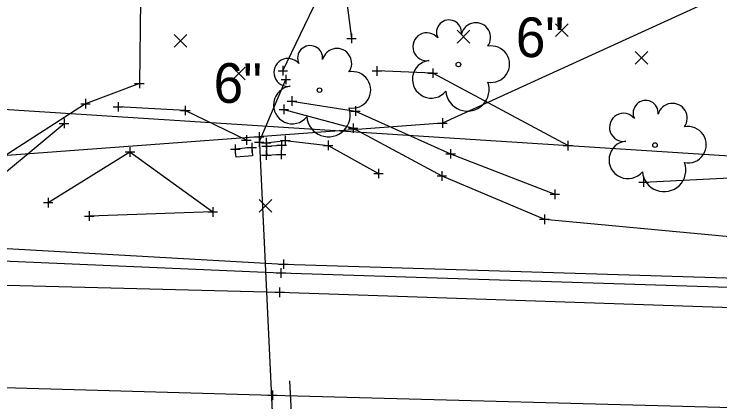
# Model space of a CAD drawing. Extents: x 2005176 to 2005823, y 572472 to 572942.
# Drawn here: x 2005497.2 to 2005571.3, y 572608.1 to 572648.8 of the extents above; entities that cross this region are included whole.
import ezdxf

# ---------------------------------------------------------------- set-up
doc = ezdxf.new("R2010")
doc.units = 0
for name, color, linetype in [('_CIVIL_CONSTRUCTION', 7, 'Continuous'), ('DR_X_Storm_Sewer', 7, 'Continuous'), ('DR_X_Text', 7, 'Continuous'), ('GE_X_Alignment_1000_Bearings', 7, 'Continuous'), ('GE_X_Alignment_1000_Cardinal_Points', 7, 'Continuous'), ('GE_X_Alignment_1000_Curve_Data', 7, 'Continuous'), ('GE_X_Alignment_100_Bearings', 7, 'Continuous'), ('GE_X_Alignment_100_Cardinal_Points', 7, 'Continuous'), ('GE_X_Alignment_100_Distances', 7, 'Continuous'), ('GE_X_Alignment_100_Stations', 7, 'Continuous'), ('GE_X_Alignment_500_Bearings', 7, 'Continuous'), ('GE_X_Alignment_500_Distances', 7, 'Continuous'), ('SC_Scratch10', 7, 'Continuous'), ('SC_Scratch8', 7, 'Continuous'), ('SV_P_Mon_Cells_Set', 7, 'Continuous'), ('SV_X_Random_Point', 7, 'Continuous'), ('SV_X_Shot_Marker', 7, 'Continuous'), ('VG_X_Text', 7, 'Continuous')]:
    doc.layers.add(name, color=color, linetype=linetype)

msp = doc.modelspace()

# ---------------------------------------------------------------- linework, layer by layer
at = {"layer": '_CIVIL_CONSTRUCTION'}
for p, q in [((2005525.415, 572643.362), (2005525.415, 572642.362)), ((2005524.915, 572642.862), (2005525.915, 572642.862)), ((2005525.415, 572642.862), (2005525.415, 572642.862)), ((2005522.925, 572636.417), (2005522.925, 572635.417)), ((2005522.425, 572635.917), (2005523.425, 572635.917)), ((2005522.925, 572635.917), (2005522.925, 572635.917))]:
    msp.add_line(p, q, dxfattribs=at)
at = {"layer": 'DR_X_Storm_Sewer'}
for p, q in [((2005525.415, 572642.862), (2005551.774, 572697.546)), ((2005522.925, 572635.917), (2005526.039, 572569.63))]:
    msp.add_line(p, q, dxfattribs=at)
at = {"layer": 'DR_X_Text'}
msp.add_line((2005527.042, 572591.446), (2005526.156, 572610.296), dxfattribs=at)
at = {"layer": 'GE_X_Alignment_1000_Bearings'}
msp.add_lwpolyline([(2005377.362, 572646.47), (2005740.514, 572623.098)], dxfattribs=at)
at = {"layer": 'GE_X_Alignment_1000_Cardinal_Points'}
msp.add_lwpolyline([(2005589.359, 572669.576), (2005577.827, 572653.684), (2005542.162, 572637.376), (2005475.268, 572632.406), (2005412.503, 572639.628), (2005455.372, 572649.173), (2005453.824, 572664.208)], dxfattribs=at)
at = {"layer": 'GE_X_Alignment_1000_Curve_Data'}
for p, q in [((2005522.149, 572634.791), (2005522.221, 572633.915)), ((2005523.761, 572633.979), (2005523.715, 572634.946)), ((2005520.512, 572633.775), (2005520.422, 572634.628)), ((2005525.234, 572634.064), (2005523.761, 572633.979)), ((2005522.221, 572633.915), (2005520.512, 572633.775))]:
    msp.add_line(p, q, dxfattribs=at)
for points in [[(2005522.149, 572634.791), (2005520.422, 572634.628)], [(2005523.715, 572634.946), (2005525.287, 572635.045), (2005525.234, 572634.064)]]:
    msp.add_lwpolyline(points, dxfattribs=at)
at = {"layer": 'GE_X_Alignment_100_Bearings'}
msp.add_lwpolyline([(2005220.703, 572626.419), (2005272.188, 572624.708), (2005322.24, 572623.496), (2005370.592, 572622.698), (2005425.14, 572621.649), (2005477.359, 572620.84), (2005525.073, 572619.597), (2005576.701, 572617.862), (2005628.145, 572615.985), (2005678.392, 572614.092), (2005728.231, 572612.033), (2005777.043, 572611.016), (2005819.95, 572609.987)], dxfattribs=at)
at = {"layer": 'GE_X_Alignment_100_Cardinal_Points'}
msp.add_lwpolyline([(2005220.502, 572615.986), (2005272.509, 572614.367), (2005322.2, 572613.202), (2005370.615, 572612.292), (2005424.944, 572611.274), (2005476.504, 572610.167), (2005524.324, 572608.789), (2005576.491, 572607.397), (2005627.688, 572605.768), (2005677.107, 572603.684), (2005728.026, 572601.917), (2005776.184, 572600.497), (2005820.14, 572599.28)], dxfattribs=at)
at = {"layer": 'GE_X_Alignment_100_Distances'}
msp.add_lwpolyline([(2005220.681, 572626.378), (2005272.188, 572624.708), (2005322.24, 572623.496), (2005370.592, 572622.698), (2005425.14, 572621.649), (2005477.359, 572620.84), (2005525.073, 572619.597), (2005576.701, 572617.862), (2005628.145, 572615.985), (2005678.392, 572614.092), (2005728.231, 572612.033), (2005777.043, 572611.016), (2005820.016, 572609.904)], dxfattribs=at)
at = {"layer": 'GE_X_Alignment_100_Stations'}
for points in [[(2005522.932, 572635.367), (2005525.735, 572641.947)], [(2005525.525, 572638.809), (2005532.797, 572636.84), (2005542.105, 572631.821), (2005552.862, 572627.266), (2005580.898, 572624.645), (2005628.272, 572621.554), (2005683.341, 572619.886), (2005735.016, 572617.808), (2005744.527, 572617.083)], [(2005222.426, 572636.471), (2005271.73, 572636.063), (2005321.627, 572634.112), (2005368.049, 572633.723), (2005426.441, 572630.349), (2005456.6, 572629.269), (2005476.492, 572629.515), (2005493.016, 572629.48), (2005502.458, 572637.333)]]:
    msp.add_lwpolyline(points, dxfattribs=at)
at = {"layer": 'GE_X_Alignment_500_Bearings'}
for points in [[(2005542.844, 572700.296), (2005523.816, 572678.945), (2005515.819, 572663.819), (2005510.488, 572650.261), (2005510.359, 572641.52), (2005504.712, 572639.398), (2005492.739, 572631.706)], [(2005550.488, 572685.468), (2005542.688, 572667.5), (2005536.366, 572658.022), (2005531.779, 572652.766), (2005532.621, 572646.264)], [(2005555.324, 572635.001), (2005541.147, 572642.612), (2005535.292, 572642.843)], [(2005526.368, 572639.679), (2005533.044, 572638.632), (2005543.024, 572634.134), (2005553.961, 572629.896)], [(2005521.586, 572635.584), (2005515.181, 572638.688), (2005508.12, 572639.078)], [(2005523.659, 572635.302), (2005525.669, 572635.53), (2005530.179, 572635.027), (2005535.449, 572632.074)], [(2005500.791, 572629.015), (2005509.369, 572634.339), (2005518.058, 572628.041), (2005505.104, 572627.603)], [(2005563.277, 572631.158), (2005581.337, 572632.069), (2005628.402, 572630.647), (2005683.066, 572631.081), (2005734.764, 572630.652)]]:
    msp.add_lwpolyline(points, dxfattribs=at)
at = {"layer": 'GE_X_Alignment_500_Distances'}
msp.add_lwpolyline([(2005220.405, 572616.044), (2005272.509, 572614.367), (2005322.2, 572613.202), (2005370.615, 572612.292), (2005424.944, 572611.274), (2005476.504, 572610.167), (2005524.324, 572608.789), (2005576.491, 572607.397), (2005627.688, 572605.768), (2005677.107, 572603.684), (2005728.026, 572601.917), (2005776.184, 572600.497), (2005820.136, 572599.258)], dxfattribs=at)
at = {"layer": 'SC_Scratch10'}
msp.add_lwpolyline([(2005220.884, 572629.15), (2005272.142, 572627.639), (2005321.829, 572626.683), (2005370.647, 572625.998), (2005424.699, 572625.916), (2005476.694, 572625.325), (2005525.491, 572622.558), (2005576.479, 572620.992), (2005628.303, 572618.679), (2005678.316, 572615.978), (2005728.346, 572614.832)], dxfattribs=at)
at = {"layer": 'SC_Scratch8'}
msp.add_lwpolyline([(2005220.896, 572628.724), (2005272.158, 572627.129), (2005321.833, 572625.738), (2005370.812, 572624.996), (2005424.978, 572624.564), (2005477.308, 572623.696), (2005525.214, 572621.632), (2005576.562, 572620.009), (2005628.235, 572617.888), (2005678.254, 572615.227), (2005728.27, 572613.254), (2005777.125, 572612.236), (2005820.016, 572611.502)], dxfattribs=at)
at = {"layer": 'SV_P_Mon_Cells_Set'}
for p, q in [((2005532.621, 572646.764), (2005532.621, 572645.764)), ((2005532.121, 572646.264), (2005533.121, 572646.264)), ((2005532.621, 572646.264), (2005532.621, 572646.264)), ((2005535.292, 572643.343), (2005535.292, 572642.343)), ((2005541.147, 572643.112), (2005541.147, 572642.112)), ((2005525.735, 572642.447), (2005525.735, 572641.447)), ((2005534.792, 572642.843), (2005535.792, 572642.843)), ((2005535.292, 572642.843), (2005535.292, 572642.843)), ((2005540.647, 572642.612), (2005541.647, 572642.612)), ((2005541.147, 572642.612), (2005541.147, 572642.612)), ((2005509.859, 572641.52), (2005510.859, 572641.52)), ((2005510.359, 572642.02), (2005510.359, 572641.02)), ((2005510.359, 572641.52), (2005510.359, 572641.52)), ((2005525.235, 572641.947), (2005526.235, 572641.947)), ((2005525.735, 572641.947), (2005525.735, 572641.947)), ((2005526.368, 572640.179), (2005526.368, 572639.179)), ((2005504.212, 572639.398), (2005505.212, 572639.398)), ((2005504.712, 572639.898), (2005504.712, 572638.898)), ((2005504.712, 572639.398), (2005504.712, 572639.398)), ((2005508.12, 572639.578), (2005508.12, 572638.578)), ((2005515.181, 572639.188), (2005515.181, 572638.188)), ((2005525.525, 572639.309), (2005525.525, 572638.309)), ((2005525.868, 572639.679), (2005526.868, 572639.679)), ((2005526.368, 572639.679), (2005526.368, 572639.679)), ((2005507.62, 572639.078), (2005508.62, 572639.078)), ((2005508.12, 572639.078), (2005508.12, 572639.078)), ((2005514.681, 572638.688), (2005515.681, 572638.688)), ((2005515.181, 572638.688), (2005515.181, 572638.688)), ((2005525.025, 572638.809), (2005526.025, 572638.809)), ((2005525.525, 572638.809), (2005525.525, 572638.809)), ((2005532.544, 572638.632), (2005533.544, 572638.632)), ((2005533.044, 572639.132), (2005533.044, 572638.132)), ((2005533.044, 572638.632), (2005533.044, 572638.632)), ((2005502.458, 572637.833), (2005502.458, 572636.833)), ((2005542.162, 572637.876), (2005542.162, 572636.876)), ((2005501.958, 572637.333), (2005502.958, 572637.333)), ((2005502.458, 572637.333), (2005502.458, 572637.333)), ((2005532.797, 572637.34), (2005532.797, 572636.34)), ((2005541.662, 572637.376), (2005542.662, 572637.376)), ((2005542.162, 572637.376), (2005542.162, 572637.376)), ((2005532.297, 572636.84), (2005533.297, 572636.84)), ((2005532.797, 572636.84), (2005532.797, 572636.84)), ((2005521.086, 572635.584), (2005522.086, 572635.584)), ((2005521.586, 572636.084), (2005521.586, 572635.084)), ((2005521.586, 572635.584), (2005521.586, 572635.584)), ((2005522.932, 572635.867), (2005522.932, 572634.867)), ((2005523.659, 572635.802), (2005523.659, 572634.802)), ((2005525.169, 572635.53), (2005526.169, 572635.53)), ((2005525.287, 572635.545), (2005525.287, 572634.545)), ((2005525.669, 572636.03), (2005525.669, 572635.03)), ((2005525.669, 572635.53), (2005525.669, 572635.53)), ((2005530.179, 572635.527), (2005530.179, 572634.527)), ((2005555.324, 572635.501), (2005555.324, 572634.501)), ((2005509.369, 572634.839), (2005509.369, 572633.839)), ((2005520.422, 572635.128), (2005520.422, 572634.128)), ((2005521.649, 572634.791), (2005522.649, 572634.791)), ((2005522.149, 572635.291), (2005522.149, 572634.291)), ((2005522.149, 572634.791), (2005522.149, 572634.791)), ((2005522.432, 572635.367), (2005523.432, 572635.367)), ((2005522.932, 572635.367), (2005522.932, 572635.367)), ((2005523.159, 572635.302), (2005524.159, 572635.302)), ((2005523.215, 572634.946), (2005524.215, 572634.946)), ((2005523.659, 572635.302), (2005523.659, 572635.302)), ((2005523.715, 572635.446), (2005523.715, 572634.446)), ((2005523.715, 572634.946), (2005523.715, 572634.946)), ((2005524.787, 572635.045), (2005525.787, 572635.045)), ((2005525.287, 572635.045), (2005525.287, 572635.045)), ((2005529.679, 572635.027), (2005530.679, 572635.027)), ((2005530.179, 572635.027), (2005530.179, 572635.027)), ((2005554.824, 572635.001), (2005555.824, 572635.001)), ((2005555.324, 572635.001), (2005555.324, 572635.001)), ((2005508.869, 572634.339), (2005509.869, 572634.339)), ((2005509.369, 572634.339), (2005509.369, 572634.339)), ((2005519.922, 572634.628), (2005520.922, 572634.628)), ((2005520.422, 572634.628), (2005520.422, 572634.628)), ((2005523.168, 572634.001), (2005524.168, 572634.001)), ((2005523.668, 572634.501), (2005523.668, 572633.501)), ((2005523.668, 572634.001), (2005523.668, 572634.001)), ((2005524.735, 572634.064), (2005525.735, 572634.064)), ((2005525.234, 572634.564), (2005525.234, 572633.564)), ((2005525.234, 572634.064), (2005525.234, 572634.064)), ((2005542.524, 572634.134), (2005543.524, 572634.134)), ((2005543.024, 572634.634), (2005543.024, 572633.634)), ((2005543.024, 572634.134), (2005543.024, 572634.134)), ((2005535.449, 572632.574), (2005535.449, 572631.574)), ((2005534.949, 572632.074), (2005535.949, 572632.074)), ((2005535.449, 572632.074), (2005535.449, 572632.074)), ((2005541.605, 572631.821), (2005542.605, 572631.821)), ((2005542.105, 572632.321), (2005542.105, 572631.321)), ((2005542.105, 572631.821), (2005542.105, 572631.821)), ((2005562.777, 572631.158), (2005563.777, 572631.158)), ((2005563.277, 572631.658), (2005563.277, 572630.658)), ((2005563.277, 572631.158), (2005563.277, 572631.158)), ((2005553.961, 572630.396), (2005553.961, 572629.396)), ((2005553.461, 572629.896), (2005554.461, 572629.896)), ((2005553.961, 572629.896), (2005553.961, 572629.896)), ((2005500.291, 572629.015), (2005501.291, 572629.015)), ((2005500.791, 572629.515), (2005500.791, 572628.515)), ((2005500.791, 572629.015), (2005500.791, 572629.015)), ((2005505.104, 572628.103), (2005505.104, 572627.103)), ((2005518.058, 572628.541), (2005518.058, 572627.541)), ((2005504.604, 572627.603), (2005505.604, 572627.603)), ((2005505.104, 572627.603), (2005505.104, 572627.603)), ((2005517.558, 572628.041), (2005518.558, 572628.041)), ((2005518.058, 572628.041), (2005518.058, 572628.041)), ((2005552.862, 572627.766), (2005552.862, 572626.766)), ((2005552.362, 572627.266), (2005553.362, 572627.266)), ((2005552.862, 572627.266), (2005552.862, 572627.266)), ((2005525.491, 572623.058), (2005525.491, 572622.058)), ((2005524.991, 572622.558), (2005525.991, 572622.558)), ((2005525.491, 572622.558), (2005525.491, 572622.558)), ((2005524.714, 572621.632), (2005525.714, 572621.632)), ((2005525.214, 572622.132), (2005525.214, 572621.132)), ((2005525.214, 572621.632), (2005525.214, 572621.632)), ((2005525.073, 572620.097), (2005525.073, 572619.097)), ((2005525.073, 572620.097), (2005525.073, 572619.097)), ((2005524.573, 572619.597), (2005525.573, 572619.597)), ((2005524.573, 572619.597), (2005525.573, 572619.597)), ((2005525.073, 572619.597), (2005525.073, 572619.597)), ((2005525.073, 572619.597), (2005525.073, 572619.597)), ((2005524.324, 572609.289), (2005524.324, 572608.289)), ((2005524.324, 572609.289), (2005524.324, 572608.289)), ((2005523.824, 572608.789), (2005524.824, 572608.789)), ((2005523.824, 572608.789), (2005524.824, 572608.789)), ((2005524.324, 572608.789), (2005524.324, 572608.789)), ((2005524.324, 572608.789), (2005524.324, 572608.789))]:
    msp.add_line(p, q, dxfattribs=at)
at = {"layer": 'SV_X_Random_Point'}
for p, q in [((2005554.034, 572646.465), (2005555.368, 572647.8)), ((2005554.034, 572647.8), (2005555.368, 572646.465)), ((2005514.014, 572645.35), (2005515.347, 572646.684)), ((2005514.014, 572646.684), (2005515.347, 572645.35)), ((2005543.711, 572645.771), (2005545.045, 572647.106)), ((2005543.711, 572647.106), (2005545.045, 572645.771)), ((2005562.4, 572643.562), (2005563.733, 572644.897)), ((2005562.4, 572644.897), (2005563.733, 572643.562)), ((2005520.119, 572641.907), (2005521.453, 572643.242)), ((2005520.119, 572643.242), (2005521.453, 572641.907)), ((2005522.943, 572628.023), (2005524.276, 572629.358)), ((2005522.943, 572629.358), (2005524.276, 572628.023))]:
    msp.add_line(p, q, dxfattribs=at)
at = {"layer": 'SV_X_Shot_Marker'}
for centre in [(2005543.839, 572643.515), (2005529.263, 572640.819), (2005564.474, 572635.057)]:
    msp.add_circle(centre, 0.24, dxfattribs=at)
for centre, radius, start, end in [((2005542.855, 572646.882), 1.317, 354.0047, 205.97412), ((2005545.665, 572646.344), 1.553, 323.82996, 165.0376), ((2005540.53, 572645.379), 1.471, 39.06254, 279.54124), ((2005528.279, 572644.186), 1.317, 354.0047, 205.97412), ((2005531.089, 572643.648), 1.553, 323.82996, 165.0376), ((2005547.299, 572643.551), 1.915, 259.14531, 101.45961), ((2005525.954, 572642.683), 1.471, 39.06254, 279.54124), ((2005540.986, 572641.966), 1.974, 96.17219, 320.57371), ((2005532.723, 572640.855), 1.915, 259.14531, 101.45961), ((2005544.785, 572640.91), 2.284, 184.94757, 19.45715), ((2005526.41, 572639.27), 1.974, 96.17219, 320.57371), ((2005563.49, 572638.425), 1.317, 354.0047, 205.97412), ((2005566.3, 572637.886), 1.553, 323.82996, 165.0376), ((2005530.209, 572638.213), 2.284, 184.94757, 19.45715), ((2005561.164, 572636.921), 1.471, 39.06254, 279.54124), ((2005567.934, 572635.093), 1.915, 259.14531, 101.45961), ((2005561.62, 572633.509), 1.974, 96.17219, 320.57371), ((2005565.42, 572632.452), 2.284, 184.94757, 19.45715)]:
    msp.add_arc(centre, radius, start, end, dxfattribs=at)

# ---------------------------------------------------------------- texts
at = {"layer": 'VG_X_Text'}
for p in [(2005549.868, 572644.291), (2005518.152, 572639.491)]:
    msp.add_text('6"', height=4.1667, dxfattribs=at).set_placement(p)

doc.saveas('drawing.dxf')
